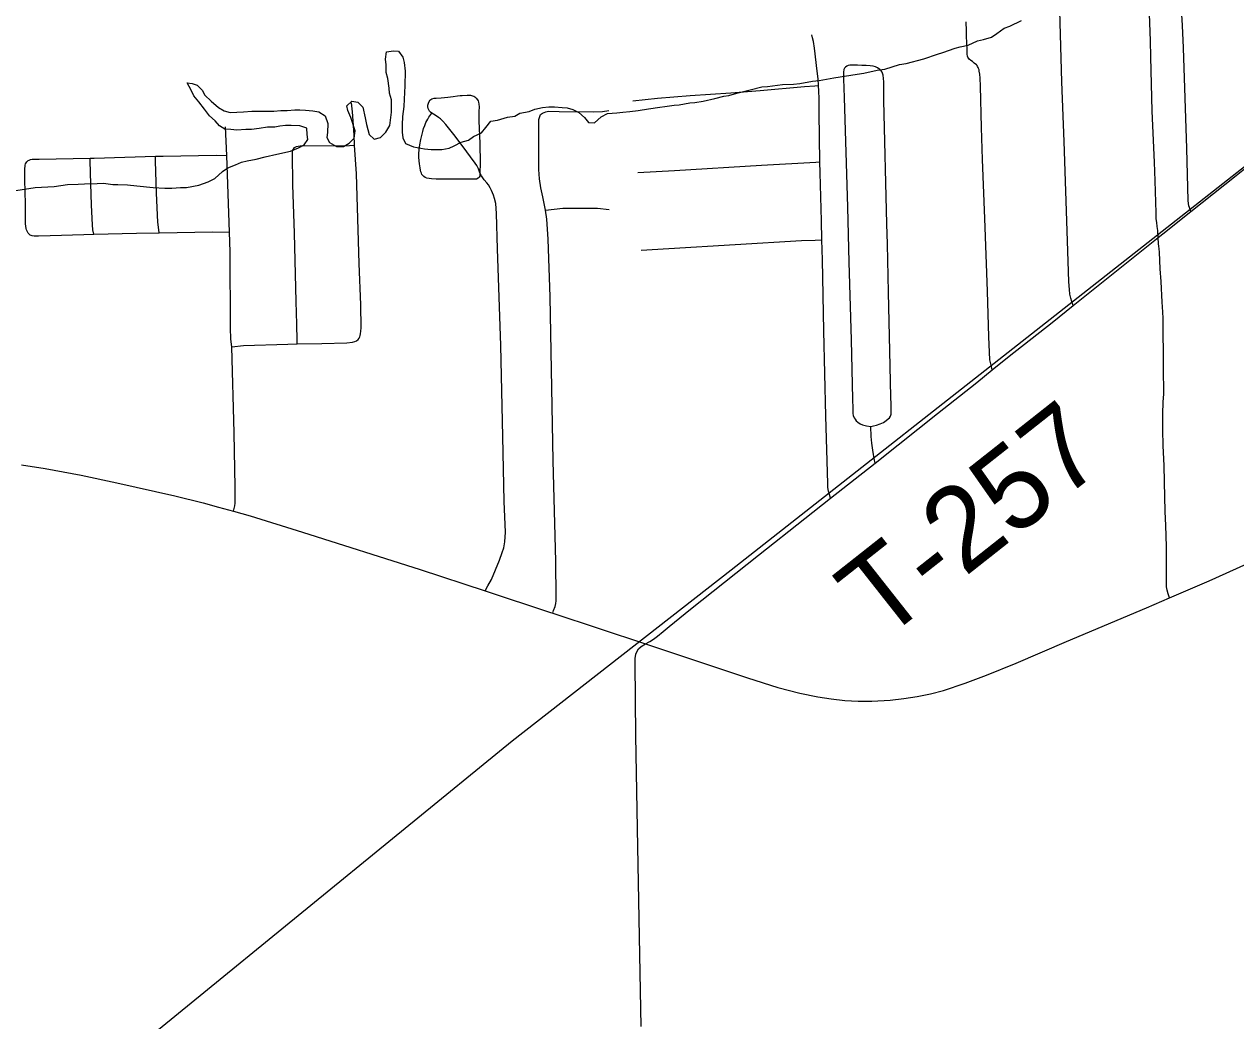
# Model space of a CAD drawing. Extents: x 0 to 34, y 0 to 22.
# Drawn here: x 7.5351 to 7.9473, y 18.7969 to 19.1358 of the extents above; entities that cross this region are included whole.
import ezdxf

# ---------------------------------------------------------------- set-up
doc = ezdxf.new("R2010")
doc.units = 0
for name, color, linetype in [('GM_X_Minor_River', 7, 'Continuous'), ('GM_X_Rail_Line', 7, 'Continuous'), ('GM_X_State_Route', 7, 'Continuous'), ('GM_X_Township_Road', 7, 'Continuous'), ('GM_X_Township_Road_Text', 7, 'Continuous')]:
    doc.layers.add(name, color=color, linetype=linetype)

msp = doc.modelspace()

# ---------------------------------------------------------------- linework, layer by layer
at = {"layer": 'GM_X_Minor_River'}
for points in [[(7.65824, 19.12205), (7.65804, 19.12395), (7.65841, 19.12642), (7.66069, 19.12681), (7.66239, 19.12663), (7.66392, 19.12455), (7.66431, 19.12284), (7.66471, 19.1198), (7.66454, 19.11486), (7.66438, 19.11029), (7.6642, 19.10782), (7.66384, 19.1044), (7.66366, 19.10155), (7.66367, 19.09908), (7.66387, 19.09718), (7.66483, 19.09528), (7.6675, 19.09415), (7.6713, 19.09341), (7.67357, 19.09323), (7.67718, 19.09325), (7.67965, 19.09364), (7.68135, 19.09441), (7.68381, 19.09575), (7.68628, 19.09633), (7.68798, 19.09767), (7.69063, 19.09882), (7.69214, 19.10073), (7.69384, 19.10283), (7.69611, 19.10322), (7.69953, 19.10418), (7.70199, 19.10458), (7.7037, 19.10553), (7.70692, 19.10612), (7.70882, 19.10689), (7.71147, 19.10747), (7.71356, 19.10767), (7.71546, 19.10768), (7.71811, 19.1075), (7.71982, 19.10732), (7.72173, 19.10676), (7.72382, 19.10582), (7.72573, 19.10412), (7.72706, 19.10241), (7.72915, 19.10223), (7.73142, 19.10433), (7.7335, 19.10548), (7.73673, 19.10569), (7.73881, 19.10589), (7.74109, 19.10609), (7.74394, 19.10648), (7.74754, 19.10707), (7.75133, 19.10765), (7.75304, 19.10785), (7.75627, 19.10825), (7.75798, 19.10844), (7.76158, 19.10903), (7.76329, 19.10923), (7.76613, 19.10962), (7.77011, 19.11059), (7.77315, 19.11137), (7.77486, 19.11156), (7.77751, 19.11234), (7.78206, 19.1135), (7.78604, 19.11447), (7.78794, 19.11466), (7.79306, 19.11526), (7.79686, 19.11546), (7.79894, 19.11567), (7.8033, 19.11645), (7.80558, 19.11665), (7.81051, 19.11762), (7.81848, 19.1188), (7.82076, 19.11919), (7.82531, 19.12016), (7.82796, 19.12055), (7.83289, 19.12209), (7.83517, 19.12248), (7.84123, 19.12403), (7.84578, 19.12557), (7.84768, 19.12615), (7.85185, 19.12769), (7.85355, 19.12808), (7.85621, 19.12866), (7.85943, 19.1302), (7.86151, 19.13059), (7.86417, 19.13136), (7.86606, 19.1327), (7.86852, 19.13442), (7.87041, 19.13519), (7.87439, 19.13711)], [(7.54531, 19.08067), (7.54986, 19.08126), (7.55347, 19.08146), (7.55556, 19.08148), (7.55992, 19.08169), (7.56201, 19.0817), (7.56524, 19.08133), (7.56695, 19.08134), (7.57018, 19.08116), (7.5734, 19.0808), (7.57891, 19.08025), (7.5829, 19.08008), (7.58537, 19.08009), (7.58821, 19.08029), (7.5903, 19.0803), (7.59447, 19.08108), (7.5977, 19.08224), (7.59997, 19.08339), (7.60261, 19.08568), (7.60432, 19.08702), (7.60697, 19.08798), (7.60905, 19.08894), (7.61095, 19.08933), (7.61398, 19.08992), (7.61702, 19.09069), (7.621, 19.09166), (7.62574, 19.09263), (7.62839, 19.09378), (7.63029, 19.09474), (7.6316, 19.09665), (7.63141, 19.09836), (7.6312, 19.10045), (7.62892, 19.1012), (7.62588, 19.10137), (7.62399, 19.10137), (7.62209, 19.10117), (7.62038, 19.10078), (7.61791, 19.10077), (7.61507, 19.10037), (7.61241, 19.09998), (7.61051, 19.09997), (7.60748, 19.09977), (7.60539, 19.09995), (7.6033, 19.10013), (7.60159, 19.10126), (7.60006, 19.10297), (7.59815, 19.10467), (7.59643, 19.10694), (7.59452, 19.1094), (7.5928, 19.11149), (7.59184, 19.11338), (7.5905, 19.11585), (7.59221, 19.11566), (7.59392, 19.1151), (7.59564, 19.1134), (7.5966, 19.11169), (7.5987, 19.10961), (7.60117, 19.10753), (7.60308, 19.1064), (7.60517, 19.10584), (7.60745, 19.10585), (7.60972, 19.10605), (7.61257, 19.10625), (7.61997, 19.10629), (7.62244, 19.10649), (7.62453, 19.1065), (7.62719, 19.1067), (7.62889, 19.10671), (7.63079, 19.10653), (7.63326, 19.10635), (7.63535, 19.10598), (7.63745, 19.10466), (7.63841, 19.102), (7.63824, 19.09896), (7.63805, 19.09725), (7.63901, 19.09554), (7.6413, 19.09422), (7.64377, 19.09423), (7.64566, 19.09538), (7.64736, 19.0971), (7.64772, 19.09957), (7.64618, 19.10413), (7.64522, 19.10641), (7.64483, 19.10811), (7.64653, 19.10964), (7.64863, 19.10927), (7.65034, 19.10757), (7.65112, 19.10396), (7.65151, 19.10168), (7.65248, 19.09827), (7.65419, 19.09675), (7.65628, 19.09733), (7.65817, 19.09905), (7.65949, 19.10134), (7.66003, 19.1059), (7.66001, 19.11008), (7.65943, 19.11236), (7.65923, 19.11407), (7.65884, 19.1173), (7.65826, 19.11939), (7.65824, 19.12205)], [(7.53222, 19.07928), (7.53886, 19.08026), (7.54531, 19.08067)]]:
    msp.add_lwpolyline(points, dxfattribs=at)
at = {"layer": 'GM_X_Rail_Line'}
msp.add_lwpolyline([(7.28965, 18.56333), (7.33819, 18.59766), (7.55551, 18.77331), (7.70112, 18.89206), (7.77562, 18.9502), (8.0118, 19.13574), (8.20934, 19.29284), (8.23098, 19.30861), (8.24767, 19.31634), (8.26684, 19.32006), (8.45882, 19.33645), (8.52713, 19.33923), (8.6072, 19.33954), (8.64677, 19.34139), (8.7358, 19.34232), (8.81, 19.34449), (8.82515, 19.34108), (8.87121, 19.33892), (8.9, 19.33972)], dxfattribs=at)
at = {"layer": 'GM_X_State_Route'}
msp.add_lwpolyline([(7.53418, 18.98596), (7.54221, 18.98468), (7.55445, 18.9824), (7.56663, 18.97984), (7.58636, 18.97536), (7.59599, 18.97297), (7.6012, 18.97159), (7.60633, 18.97015), (7.61193, 18.96857), (7.62977, 18.96307), (7.66977, 18.95031), (7.69189, 18.94306), (7.71411, 18.93578), (7.7149, 18.93552), (7.74651, 18.92509), (7.78115, 18.91348), (7.79152, 18.91025), (7.79901, 18.90825), (7.80506, 18.90699), (7.80964, 18.90632), (7.81426, 18.90585), (7.81889, 18.90562), (7.82352, 18.90562), (7.8297, 18.90595), (7.83432, 18.90642), (7.8389, 18.90712), (7.84344, 18.90804), (7.84792, 18.90924), (7.85526, 18.91168), (7.86253, 18.91437), (7.87258, 18.91851), (7.88972, 18.92582), (7.91688, 18.93733), (7.92476, 18.94069), (7.93831, 18.94648), (7.95103, 18.95224)], dxfattribs=at)
at = {"layer": 'GM_X_Township_Road'}
for p, q in [((7.60399, 19.09116), (7.60357, 19.10088)), ((7.60489, 19.06514), (7.60399, 19.09116)), ((7.89193, 19.0401), (7.9209, 19.06328))]:
    msp.add_line(p, q, dxfattribs=at)
for points in [[(7.93201, 19.07208), (7.93154, 19.07348), (7.93134, 19.07409), (7.93122, 19.07483), (7.93113, 19.07584), (7.93065, 19.09352), (7.93007, 19.11069), (7.92952, 19.12776), (7.9292, 19.13539), (7.92866, 19.14466)], [(7.89193, 19.0401), (7.89151, 19.04147), (7.89116, 19.04263), (7.89089, 19.04396), (7.89071, 19.04556), (7.89055, 19.04816), (7.89007, 19.06216), (7.88895, 19.09589), (7.88817, 19.11625), (7.8874, 19.14033), (7.88736, 19.14143)], [(7.9209, 19.06328), (7.92075, 19.06566), (7.92058, 19.06704), (7.9204, 19.06839), (7.92027, 19.06967), (7.9202, 19.07167), (7.91988, 19.08251), (7.91961, 19.0889), (7.91888, 19.1062), (7.9184, 19.12471), (7.91828, 19.13011), (7.91792, 19.13934), (7.91789, 19.14022), (7.91778, 19.14094), (7.91761, 19.14124)], [(7.86446, 19.01826), (7.86404, 19.01987), (7.86382, 19.02071), (7.86367, 19.02164), (7.86333, 19.0295), (7.86279, 19.04502), (7.86191, 19.06974), (7.86116, 19.08984), (7.86083, 19.10067), (7.86044, 19.1147), (7.86035, 19.11741), (7.86019, 19.11886), (7.86005, 19.11983), (7.85996, 19.12026), (7.85982, 19.12071), (7.85967, 19.12109), (7.85949, 19.12147), (7.85927, 19.12178), (7.85906, 19.12202), (7.85835, 19.1226), (7.85769, 19.12309), (7.85715, 19.12349), (7.85665, 19.12392), (7.85635, 19.12424), (7.85616, 19.12457), (7.85603, 19.12499), (7.85596, 19.12562), (7.85587, 19.1273), (7.85582, 19.12939), (7.85573, 19.13187), (7.85572, 19.13358), (7.85561, 19.13657)], [(7.80536, 19.11495), (7.80518, 19.11725), (7.80492, 19.1199), (7.80395, 19.12762), (7.80359, 19.12989), (7.80333, 19.13113), (7.80302, 19.13215)], [(7.82877, 19.06102), (7.8286, 19.06793), (7.82761, 19.1099), (7.82757, 19.1141), (7.82752, 19.11618), (7.82744, 19.11739), (7.82731, 19.11847), (7.82703, 19.11946), (7.82665, 19.12), (7.82619, 19.12046), (7.82544, 19.121), (7.8247, 19.12134), (7.82395, 19.1215), (7.82287, 19.12163), (7.82151, 19.12173), (7.82007, 19.12181), (7.81858, 19.12187), (7.81713, 19.12187), (7.81602, 19.12189), (7.81543, 19.12176), (7.815, 19.12158), (7.81452, 19.12125), (7.81417, 19.1209), (7.81393, 19.12038), (7.81384, 19.1195), (7.81384, 19.11842), (7.81384, 19.11722), (7.81405, 19.11085), (7.81525, 19.07354), (7.8157, 19.05489), (7.81643, 19.02848), (7.81694, 19.00827), (7.81698, 19.00515), (7.81706, 19.00345), (7.81718, 19.0027), (7.81747, 19.00191), (7.81776, 19.00145), (7.81814, 19.00095), (7.81876, 19.00041), (7.81955, 18.99991), (7.8203, 18.99958), (7.82163, 18.99921), (7.82309, 18.99904)], [(7.74214, 19.10977), (7.75056, 19.11062), (7.76171, 19.11155), (7.7755, 19.11249), (7.78554, 19.11326), (7.80061, 19.11462), (7.80409, 19.11488), (7.80536, 19.11495)], [(7.80576, 19.089), (7.80559, 19.10571), (7.80551, 19.11054), (7.80541, 19.11305), (7.80536, 19.11495)], [(7.67376, 19.10555), (7.67331, 19.10591), (7.67296, 19.10625), (7.67271, 19.10664), (7.67254, 19.10712), (7.67244, 19.10769), (7.67246, 19.1083), (7.6726, 19.10894), (7.67284, 19.10952), (7.67316, 19.11001), (7.67343, 19.11025), (7.67373, 19.11044), (7.67459, 19.11062), (7.67521, 19.11069), (7.67696, 19.11079), (7.6792, 19.11096), (7.68102, 19.11122), (7.68246, 19.11143), (7.68341, 19.11154), (7.68405, 19.1116), (7.68579, 19.11168), (7.68634, 19.11168), (7.68699, 19.11163), (7.68766, 19.1115), (7.68805, 19.11132), (7.68845, 19.11107), (7.68886, 19.11065), (7.68928, 19.11009), (7.68949, 19.10973), (7.68966, 19.10932), (7.68982, 19.10867), (7.68986, 19.10775), (7.68981, 19.10611), (7.6898, 19.10299), (7.69007, 19.09525), (7.69022, 19.0886), (7.69012, 19.0853)], [(7.64752, 19.09462), (7.64738, 19.09816), (7.64682, 19.10596), (7.64644, 19.10907)], [(7.71077, 19.10507), (7.71139, 19.10557), (7.71198, 19.10582), (7.71257, 19.10602), (7.71344, 19.1062), (7.71711, 19.10614), (7.72882, 19.10596), (7.73183, 19.10616), (7.73399, 19.10641)], [(7.69012, 19.0853), (7.69012, 19.08445), (7.69006, 19.0841), (7.68992, 19.08375), (7.68952, 19.0834), (7.68892, 19.08315), (7.68765, 19.08307), (7.67995, 19.08312), (7.67525, 19.08316), (7.67371, 19.08325), (7.67284, 19.08334), (7.67207, 19.0835), (7.67153, 19.08369), (7.67107, 19.084), (7.6707, 19.08434), (7.67042, 19.08475), (7.67024, 19.08513), (7.67006, 19.08565), (7.66992, 19.0862), (7.66979, 19.08691), (7.66957, 19.08838), (7.66947, 19.08937), (7.66937, 19.09057), (7.66941, 19.09175), (7.66952, 19.0932), (7.66971, 19.09475), (7.67001, 19.09655), (7.67066, 19.0993), (7.67099, 19.10038), (7.67136, 19.1014), (7.67174, 19.10233), (7.67203, 19.10292), (7.67239, 19.10355), (7.67274, 19.10415), (7.67376, 19.10555)], [(7.69012, 19.0853), (7.68961, 19.08662), (7.68904, 19.08776), (7.68852, 19.08855), (7.68411, 19.0946), (7.68131, 19.0983), (7.67851, 19.10175), (7.67754, 19.10283), (7.67671, 19.10362), (7.67601, 19.1041), (7.67491, 19.10485), (7.67376, 19.10555)], [(7.71249, 19.07256), (7.71149, 19.0771), (7.71086, 19.08019), (7.7104, 19.08327), (7.71013, 19.08645), (7.71013, 19.09107), (7.71019, 19.10267), (7.71021, 19.10344), (7.71037, 19.10412), (7.71077, 19.10507)], [(7.62797, 19.02709), (7.62795, 19.02825), (7.62785, 19.03381), (7.62765, 19.04146), (7.62705, 19.0647), (7.62645, 19.08119), (7.62632, 19.09179), (7.62637, 19.09242), (7.62652, 19.09295), (7.62667, 19.09335), (7.62708, 19.09387)], [(7.62708, 19.09387), (7.62771, 19.09421), (7.62834, 19.09435), (7.62902, 19.09444), (7.62978, 19.09446), (7.64572, 19.0946), (7.64752, 19.09462)], [(7.64871, 19.02855), (7.6491, 19.02905), (7.64932, 19.02953), (7.64945, 19.02998), (7.64956, 19.03045), (7.64966, 19.03143), (7.64968, 19.03257), (7.64958, 19.04041), (7.649, 19.05445), (7.6481, 19.08497), (7.64752, 19.09462)], [(7.53595, 19.089), (7.53644, 19.08942), (7.53674, 19.08956), (7.53727, 19.08976), (7.53779, 19.08987), (7.54019, 19.08997), (7.5575, 19.09026)], [(7.5575, 19.09026), (7.55892, 19.09028), (7.57977, 19.09091)], [(7.55878, 19.06435), (7.55847, 19.06583), (7.55832, 19.06756), (7.55796, 19.07424), (7.5576, 19.08526), (7.55752, 19.08942), (7.5575, 19.09026)], [(7.57977, 19.09091), (7.58241, 19.09099), (7.60037, 19.0913), (7.60399, 19.09116)], [(7.58104, 19.06486), (7.5809, 19.06592), (7.58057, 19.06854), (7.58008, 19.07836), (7.57981, 19.0894), (7.57977, 19.09091)], [(7.53644, 19.0647), (7.53604, 19.06539), (7.53585, 19.06588), (7.53575, 19.06638), (7.53557, 19.06791), (7.53551, 19.06992), (7.53549, 19.07476), (7.53531, 19.08291), (7.53531, 19.08595), (7.53535, 19.08683), (7.53539, 19.08742), (7.53545, 19.0879), (7.53557, 19.08837), (7.53595, 19.089)], [(7.74382, 19.08536), (7.75631, 19.08608), (7.78599, 19.08787), (7.80444, 19.08892), (7.80576, 19.089)], [(7.80647, 19.06243), (7.8064, 19.06892), (7.8059, 19.08525), (7.80576, 19.089)], [(7.93201, 19.07208), (7.94748, 19.08433), (7.9526, 19.08842)], [(7.69189, 18.94306), (7.69283, 18.94476), (7.69405, 18.94697), (7.69543, 18.95019), (7.69682, 18.95357), (7.69776, 18.95617), (7.69826, 18.95773), (7.69864, 18.95978), (7.69881, 18.96305), (7.69842, 18.97352), (7.69792, 18.99558), (7.6972, 19.0265), (7.69614, 19.05936), (7.69583, 19.07139), (7.69569, 19.07312), (7.69555, 19.07478), (7.69513, 19.07651), (7.69477, 19.07765), (7.69412, 19.07925), (7.69364, 19.0802), (7.69306, 19.08115), (7.69252, 19.08185), (7.69163, 19.08294), (7.69071, 19.08424), (7.69012, 19.0853)], [(7.71249, 19.07256), (7.71539, 19.07293), (7.7183, 19.0732), (7.72419, 19.07321), (7.72818, 19.07327), (7.73018, 19.07321), (7.73408, 19.07275)], [(7.7149, 18.93552), (7.71523, 18.9364), (7.71574, 18.93775), (7.71596, 18.9388), (7.71605, 18.93965), (7.7161, 18.94084), (7.71595, 18.95316), (7.71511, 18.98729), (7.71464, 19.01211), (7.71399, 19.04314), (7.71331, 19.06268), (7.7129, 19.06949), (7.71249, 19.07256)], [(7.9209, 19.06328), (7.92244, 19.0645), (7.93201, 19.07208)], [(7.58104, 19.06486), (7.59924, 19.06523), (7.60489, 19.06514)], [(7.60568, 19.02612), (7.60542, 19.02873), (7.60527, 19.03252), (7.60513, 19.0584), (7.60489, 19.06514)], [(7.53644, 19.0647), (7.53702, 19.06422), (7.53768, 19.06397), (7.53849, 19.06388), (7.53991, 19.06383), (7.54397, 19.06392), (7.55543, 19.06427), (7.55878, 19.06435)], [(7.55878, 19.06435), (7.5733, 19.0647), (7.58104, 19.06486)], [(7.74505, 19.05897), (7.75439, 19.05948), (7.79953, 19.06227), (7.8042, 19.06238), (7.80647, 19.06243)], [(7.80946, 18.97462), (7.80904, 18.97591), (7.80875, 18.97701), (7.80856, 18.97819), (7.80848, 18.97964), (7.80785, 19.00249), (7.80718, 19.03158), (7.80665, 19.05573), (7.80647, 19.06243)], [(7.82309, 18.99904), (7.824, 18.99916), (7.82512, 18.99942), (7.82632, 18.99986), (7.82745, 19.0004), (7.8284, 19.00107), (7.82905, 19.00155), (7.8295, 19.00199), (7.8298, 19.00245), (7.82995, 19.00282), (7.83001, 19.00323), (7.8301, 19.00414), (7.8301, 19.00526), (7.83006, 19.00642), (7.82998, 19.00907), (7.82965, 19.02462), (7.82917, 19.04473), (7.82877, 19.06102)], [(7.92476, 18.94069), (7.92434, 18.94212), (7.92399, 18.94329), (7.92378, 18.94441), (7.92371, 18.94565), (7.92373, 18.94825), (7.92377, 18.95222), (7.92373, 18.95813), (7.92352, 18.9653), (7.9233, 18.97009), (7.92308, 18.98019), (7.92295, 18.98576), (7.92265, 18.99241), (7.92252, 18.99781), (7.92247, 19.00329), (7.92265, 19.00726), (7.92278, 19.01011), (7.92273, 19.01891), (7.92256, 19.03579), (7.92251, 19.03791), (7.92238, 19.03964), (7.9223, 19.04132), (7.92189, 19.04836), (7.92161, 19.05257), (7.92134, 19.05823), (7.92123, 19.05937), (7.92113, 19.06034), (7.92103, 19.06117), (7.9209, 19.06328)], [(7.86446, 19.01826), (7.87022, 19.0229), (7.8848, 19.03439), (7.89193, 19.0401)], [(7.62797, 19.02709), (7.63637, 19.02724), (7.64483, 19.02746), (7.6468, 19.02763), (7.64761, 19.02786), (7.64812, 19.02808), (7.64871, 19.02855)], [(7.60568, 19.02612), (7.60966, 19.02654), (7.62478, 19.02703), (7.62797, 19.02709)], [(7.60633, 18.97015), (7.60678, 18.97203), (7.60689, 18.97293), (7.60692, 18.97376), (7.60691, 18.9745), (7.60687, 18.97628), (7.60685, 18.97838), (7.60647, 18.99679), (7.60568, 19.02612)], [(7.8246, 18.98657), (7.83247, 18.99277), (7.84584, 19.00344), (7.85919, 19.01401), (7.86446, 19.01826)], [(7.8246, 18.98657), (7.82429, 18.98815), (7.82405, 18.98943), (7.82379, 18.99097), (7.82346, 18.99334), (7.82325, 18.99563), (7.82309, 18.99904)], [(7.80946, 18.97462), (7.81781, 18.98123), (7.8246, 18.98657)], [(7.74651, 18.92509), (7.74798, 18.92591), (7.74915, 18.9266), (7.75055, 18.92766), (7.75248, 18.92924), (7.75449, 18.93095), (7.76175, 18.93682), (7.78487, 18.95521), (7.80074, 18.96772), (7.80946, 18.97462)], [(7.74503, 18.79495), (7.74391, 18.85608), (7.74319, 18.8938), (7.74297, 18.91856), (7.74301, 18.92012), (7.74323, 18.92154), (7.74362, 18.92262), (7.74414, 18.9234), (7.74504, 18.92418), (7.74651, 18.92509)]]:
    msp.add_lwpolyline(points, dxfattribs=at)

# ---------------------------------------------------------------- texts
at = {"layer": 'GM_X_Township_Road_Text'}
msp.add_text('T-257', height=0.028409, rotation=38.2672, dxfattribs=at).set_placement((7.82685, 18.9254))

doc.saveas('drawing.dxf')
